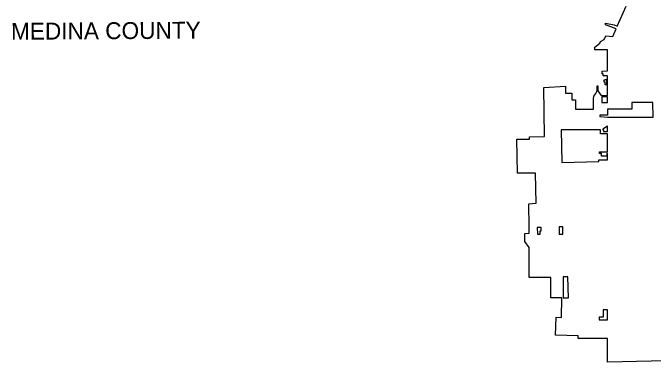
# Model space of a CAD drawing. Extents: x 2010165 to 2382125, y 1060529 to 1407316.
# Drawn here: x 2114534 to 2152412, y 1172256 to 1192922 of the extents above; entities that cross this region are included whole.
import ezdxf

# ---------------------------------------------------------------- set-up
doc = ezdxf.new("R2010")
doc.units = 0
doc.layers.add('GM_X_Adjacent_County_Text', color=7, linetype='Continuous')
doc.layers.add('GM_X_Corporation', color=7, linetype='Continuous')

msp = doc.modelspace()

# ---------------------------------------------------------------- linework, layer by layer
at = {"layer": 'GM_X_Corporation'}
msp.add_lwpolyline([(2154967, 1172367), (2152296, 1172309), (2149716, 1172256), (2149714, 1173649), (2147980, 1173649), (2147980, 1173814), (2146629, 1173864), (2146667, 1174910), (2146990, 1174907), (2147004, 1176071), (2146361, 1176071), (2146361, 1177260), (2145713, 1177263), (2145073, 1177263), (2145074, 1179034), (2144825, 1179403), (2144825, 1179873), (2145074, 1179881), (2145074, 1180250), (2145049, 1181629), (2145484, 1181661), (2145455, 1183440), (2144379, 1183443), (2144356, 1185446), (2145105, 1185450), (2145102, 1185591), (2145979, 1185600), (2145952, 1188511), (2147220, 1188577), (2147224, 1188171), (2147600, 1188174), (2147604, 1187769), (2147819, 1187771), (2147824, 1187220), (2148890, 1187229), (2148880, 1187882), (2148895, 1187949), (2148911, 1187990), (2148955, 1188070), (2149014, 1188158), (2149069, 1188259), (2149096, 1188371), (2149094, 1188607), (2149145, 1188608), (2149146, 1188301), (2149335, 1188031), (2149705, 1188031), (2149706, 1188612), (2149706, 1188668), (2149572, 1188668), (2149572, 1188823), (2149507, 1188823), (2149507, 1188961), (2149575, 1188961), (2149575, 1188974), (2149707, 1188974), (2149709, 1189199), (2149455, 1189191), (2149455, 1189321), (2149402, 1189320), (2149403, 1189477), (2149710, 1189482), (2149717, 1190739), (2148957, 1190739), (2148965, 1190894), (2149259, 1191130), (2149302, 1191223), (2149505, 1191348), (2149608, 1191559), (2150017, 1191529), (2150216, 1191975), (2149591, 1192202), (2149589, 1192312), (2150097, 1192204), (2150283, 1192125), (2150812, 1193309)], dxfattribs=at)
for points in [[(2149656, 1188673), (2149706, 1188673), (2149707, 1188969), (2149657, 1188969)], [(2149374, 1187608), (2149709, 1187608), (2149708, 1187952), (2149374, 1187952)], [(2149260, 1186795), (2149712, 1186755), (2152404, 1186754), (2152388, 1187620), (2151141, 1187612), (2151146, 1187229), (2149710, 1187221), (2149710, 1186868), (2149260, 1186868)], [(2146966, 1185999), (2147003, 1184076), (2149199, 1184118), (2149197, 1184218), (2149716, 1184229), (2149718, 1184598), (2149668, 1184598), (2149667, 1184449), (2149347, 1184450), (2149347, 1184599), (2149239, 1184600), (2149240, 1184708), (2149719, 1184706), (2149715, 1185763), (2149296, 1185763), (2149296, 1185999)], [(2149426, 1186033), (2149427, 1185999), (2149482, 1185999), (2149482, 1185905), (2149715, 1185904), (2149715, 1186222)], [(2145554, 1180226), (2145562, 1179829), (2145724, 1179829), (2145724, 1180020), (2145785, 1180020), (2145785, 1180231)], [(2146845, 1179834), (2147073, 1179834), (2147073, 1180259), (2146845, 1180254)], [(2147079, 1177298), (2147086, 1176068), (2147407, 1176064), (2147369, 1177303)], [(2149213, 1174766), (2149713, 1174766), (2149713, 1175346), (2149449, 1175346), (2149449, 1174916), (2149213, 1174916)]]:
    msp.add_lwpolyline(points, close=True, dxfattribs=at)

# ---------------------------------------------------------------- texts
at = {"layer": 'GM_X_Adjacent_County_Text'}
msp.add_text('MEDINA COUNTY', height=1000, rotation=0.3673, dxfattribs=at).set_placement((2114431, 1191324))

doc.saveas('drawing.dxf')
